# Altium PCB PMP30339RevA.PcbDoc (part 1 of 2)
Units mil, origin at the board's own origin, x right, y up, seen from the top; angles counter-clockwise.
Board outline 3000 x 2600 mil, 4 copper layers (Top Layer, Signal Layer 1, Signal Layer 2, Bottom Layer), stack 61.2 mil thick; 113 components, 43 nets, 222 pads, 187 vias.
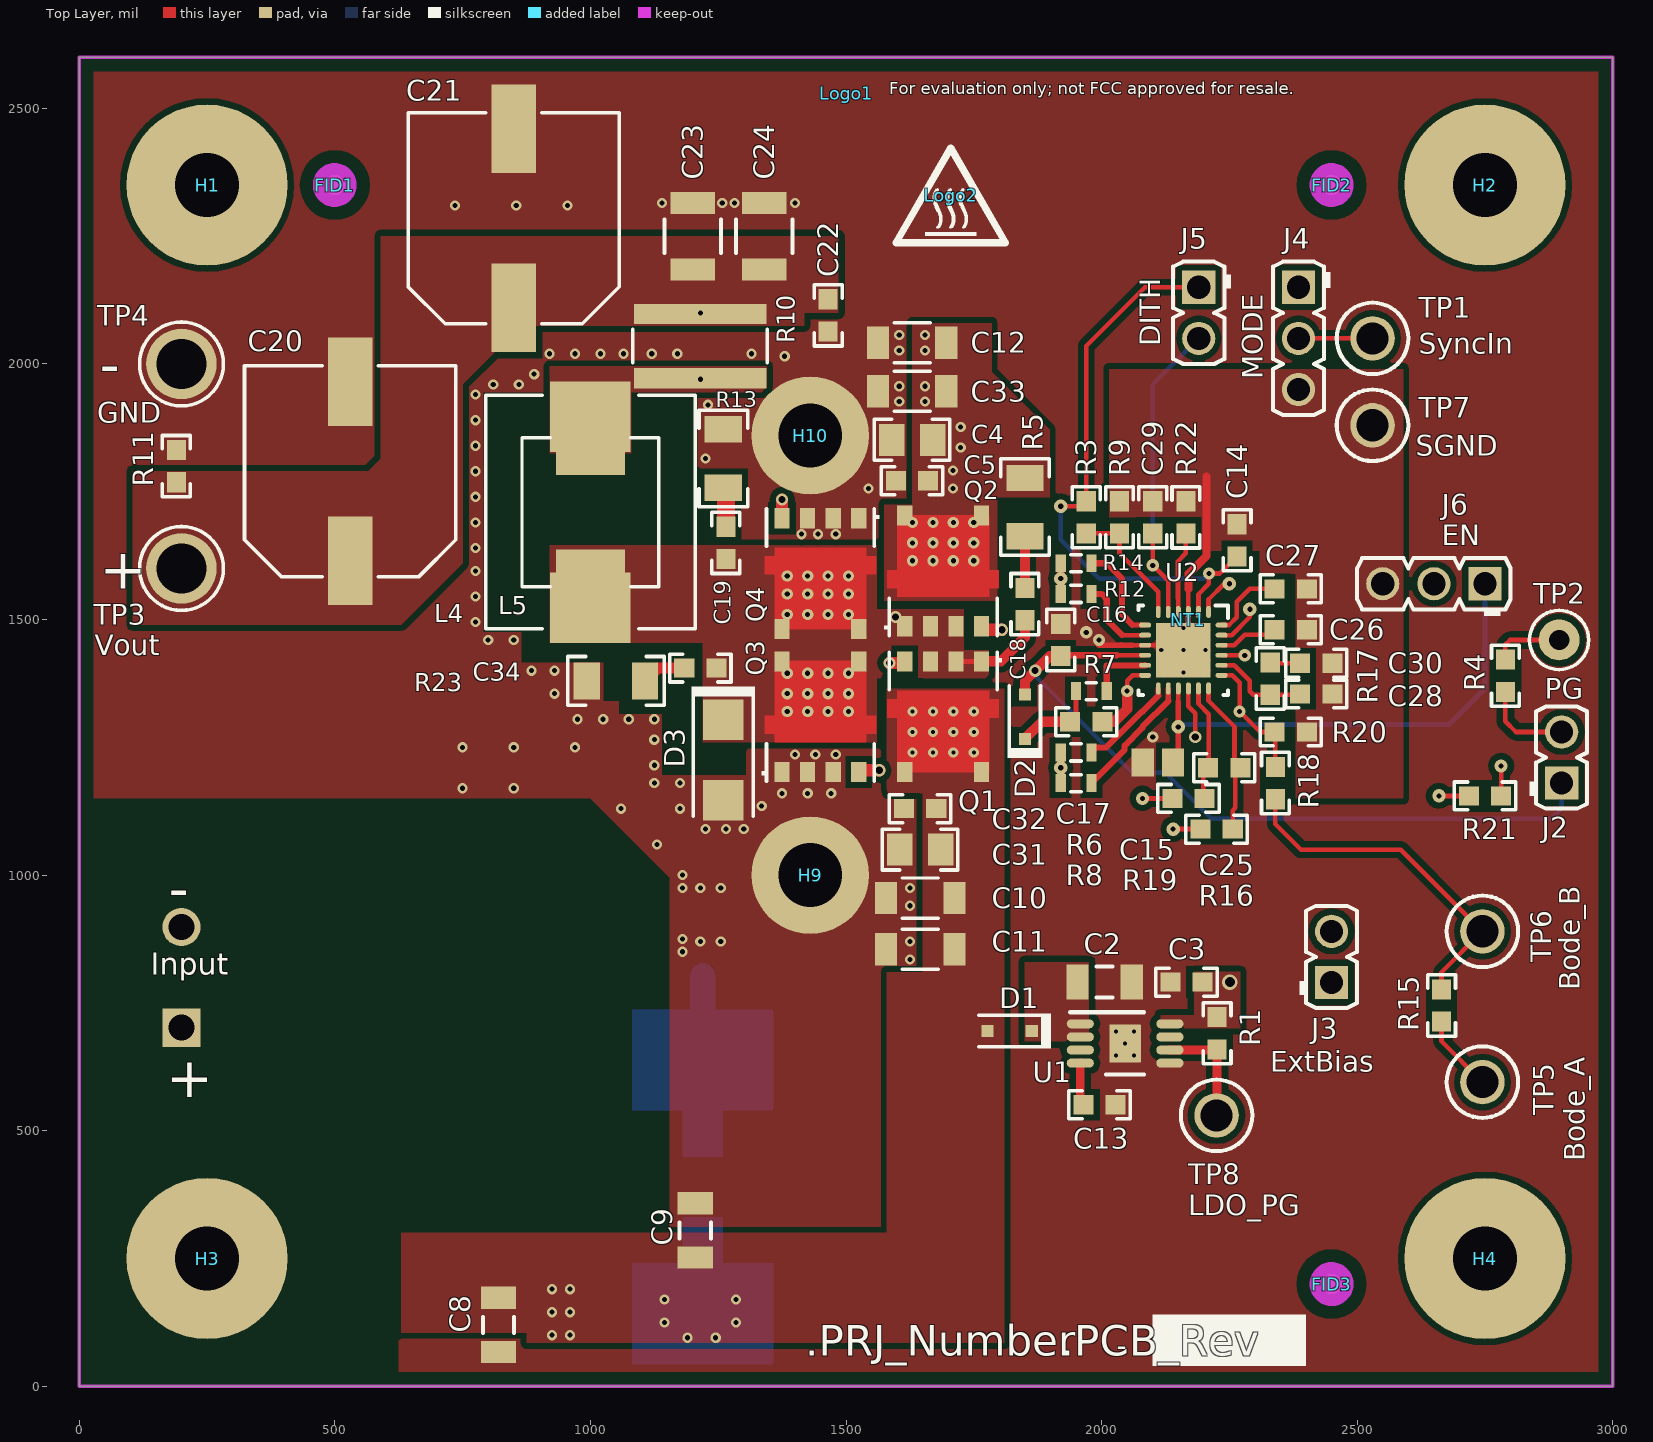
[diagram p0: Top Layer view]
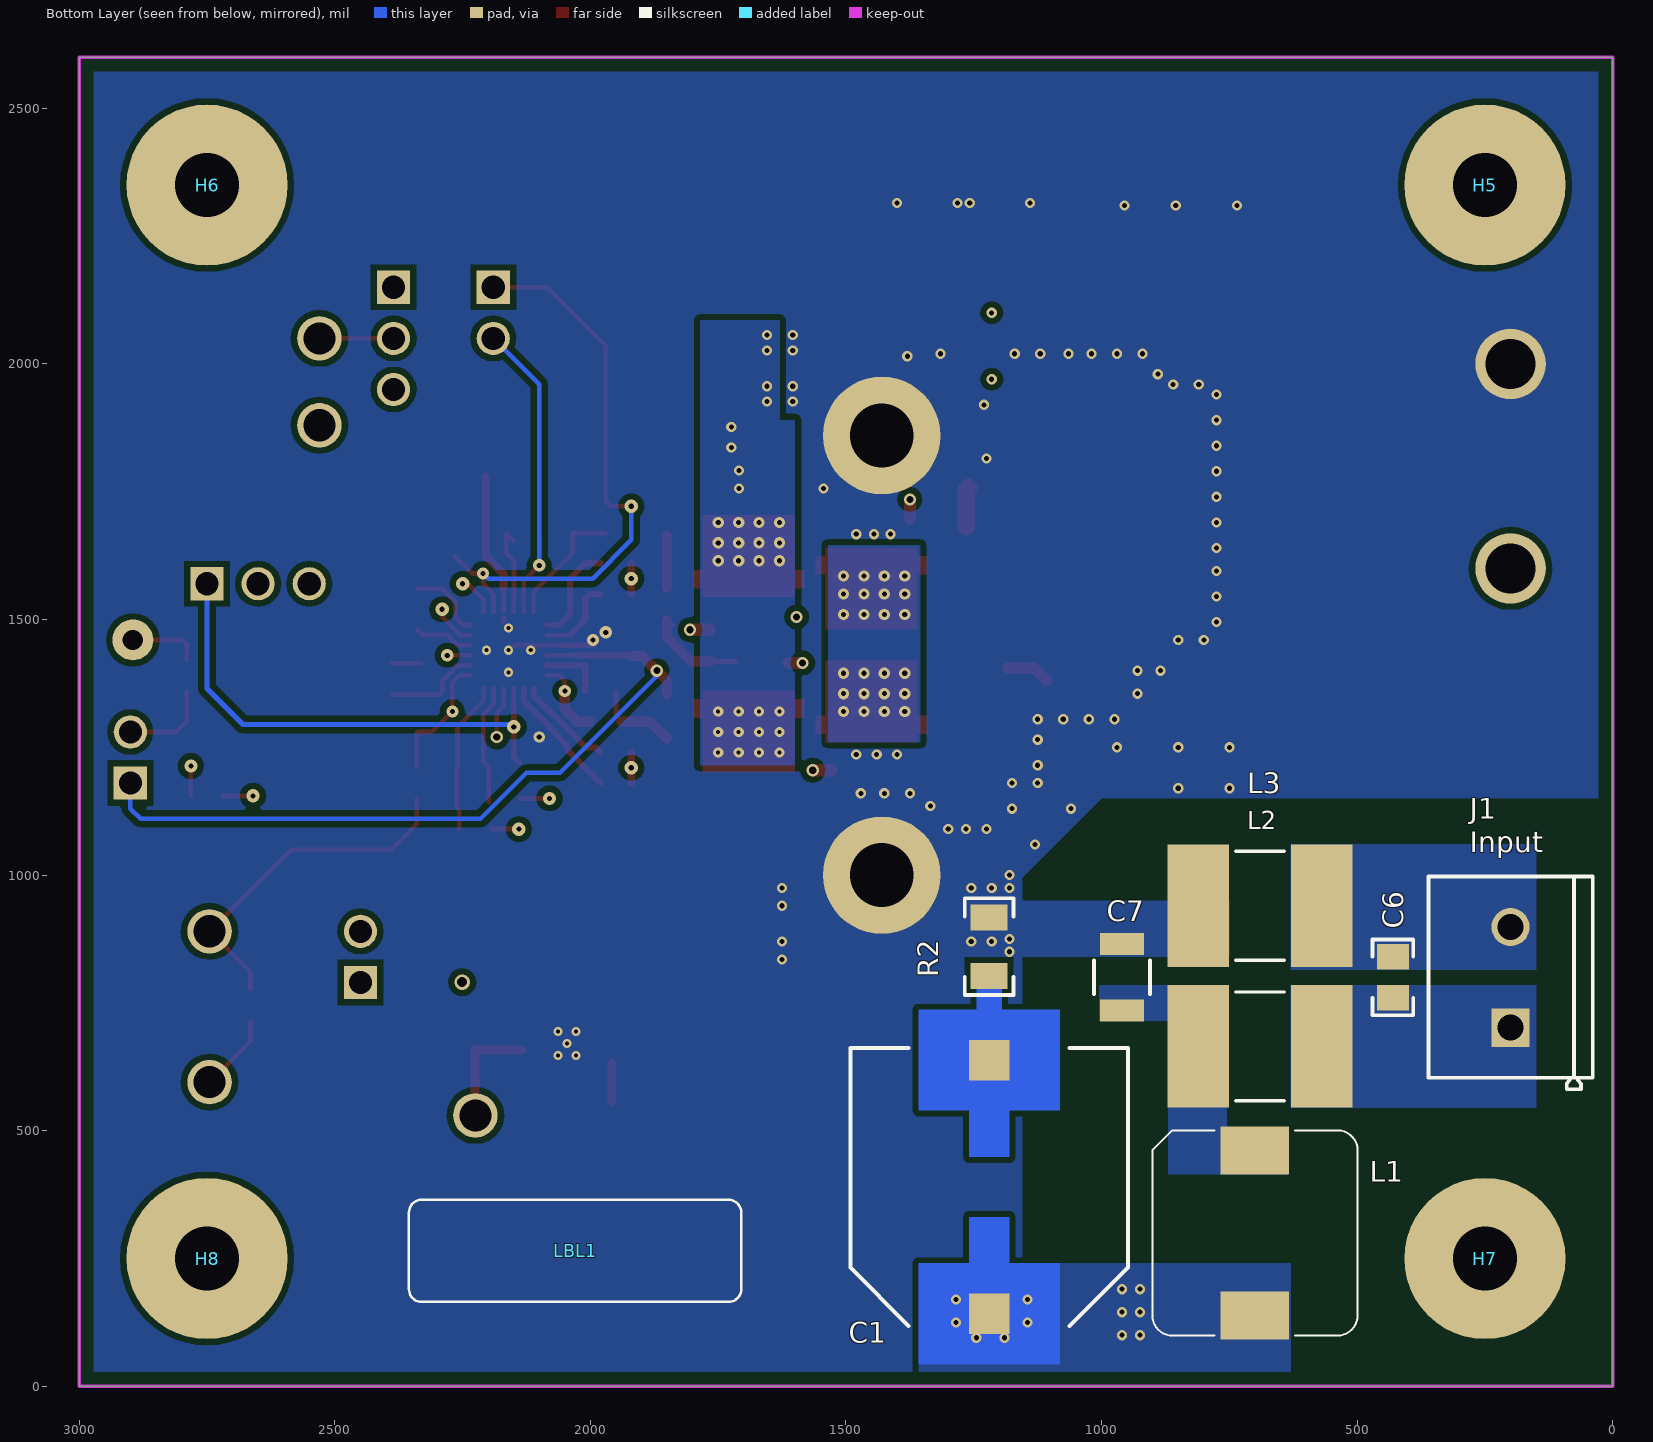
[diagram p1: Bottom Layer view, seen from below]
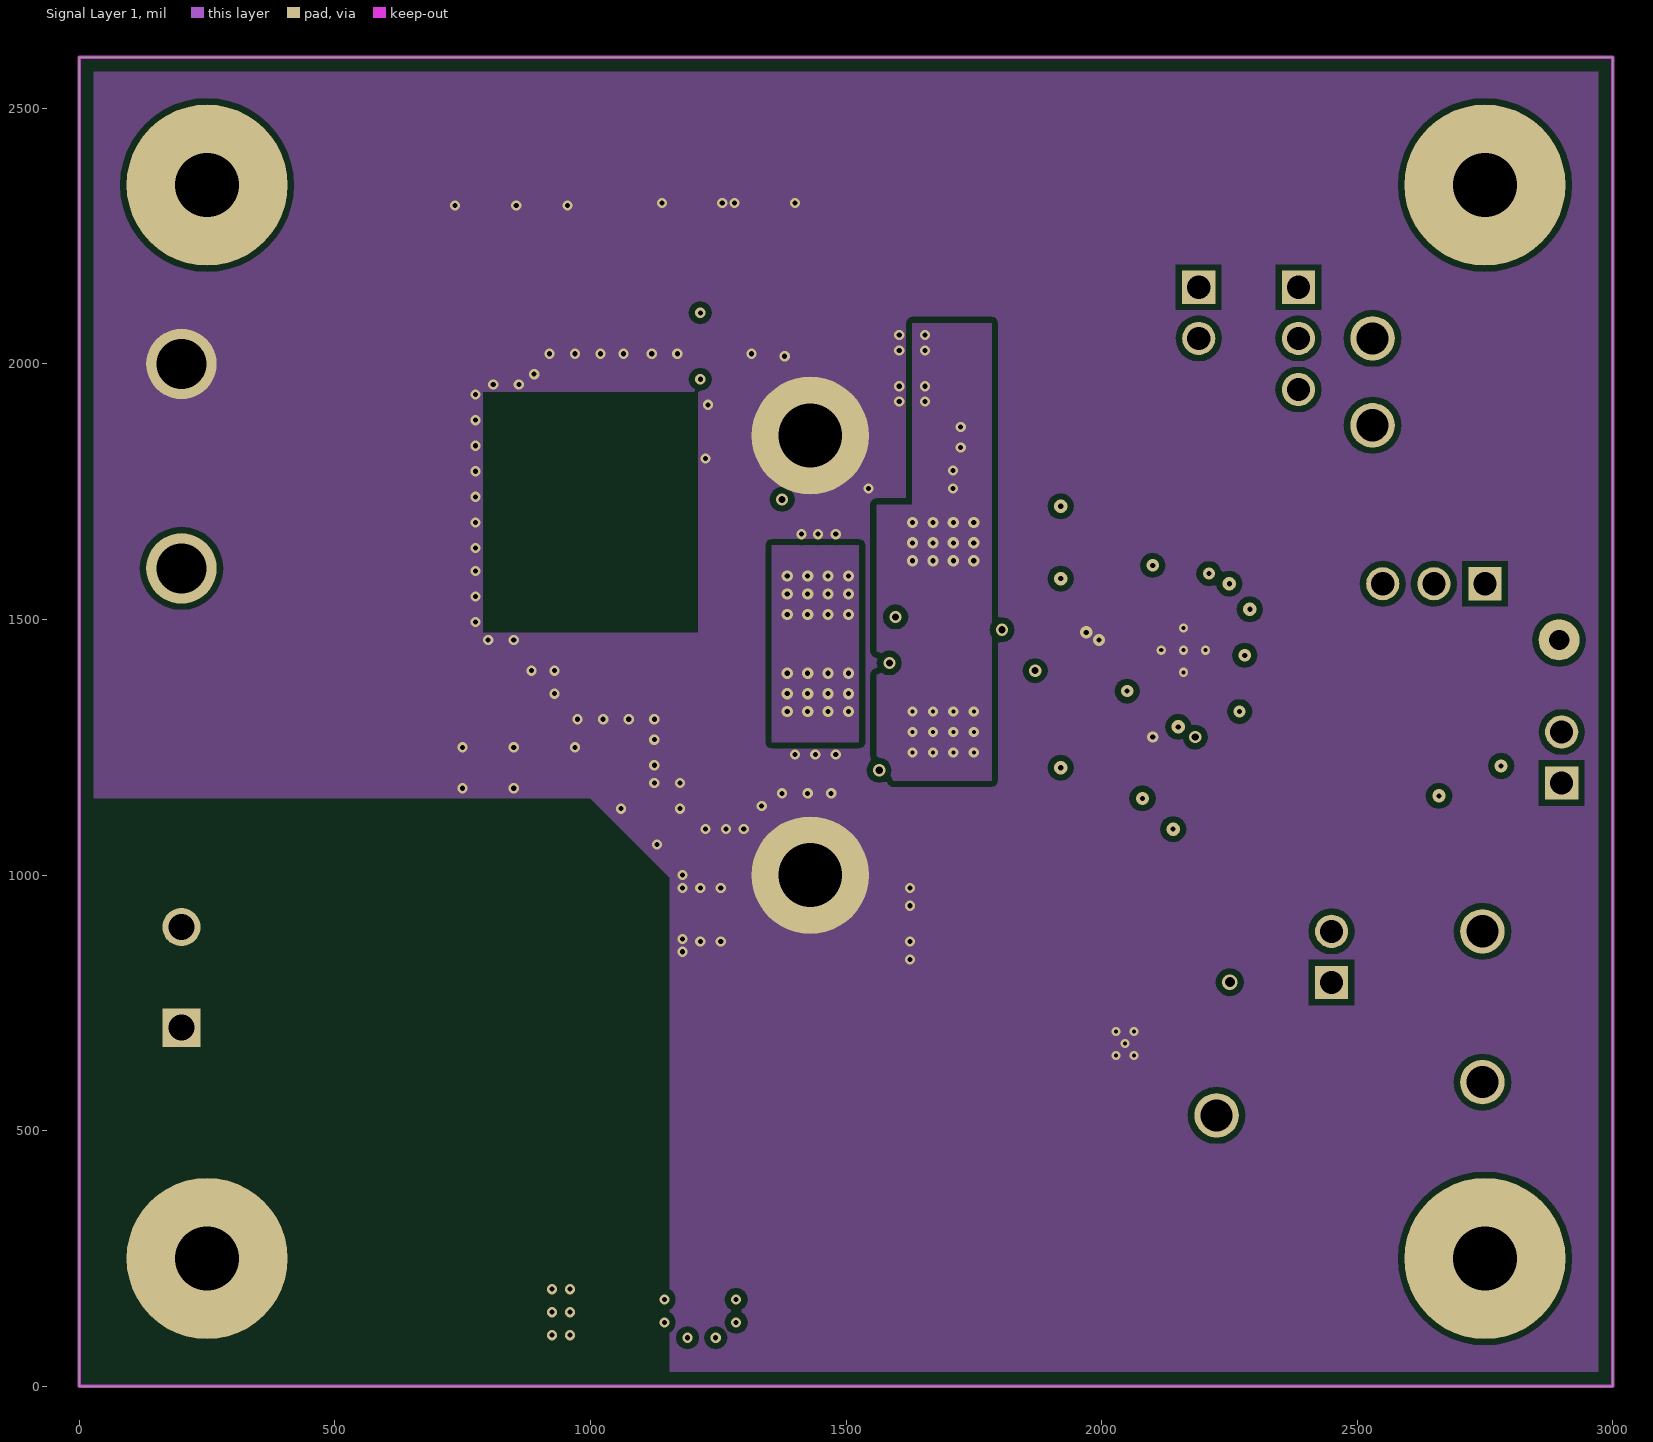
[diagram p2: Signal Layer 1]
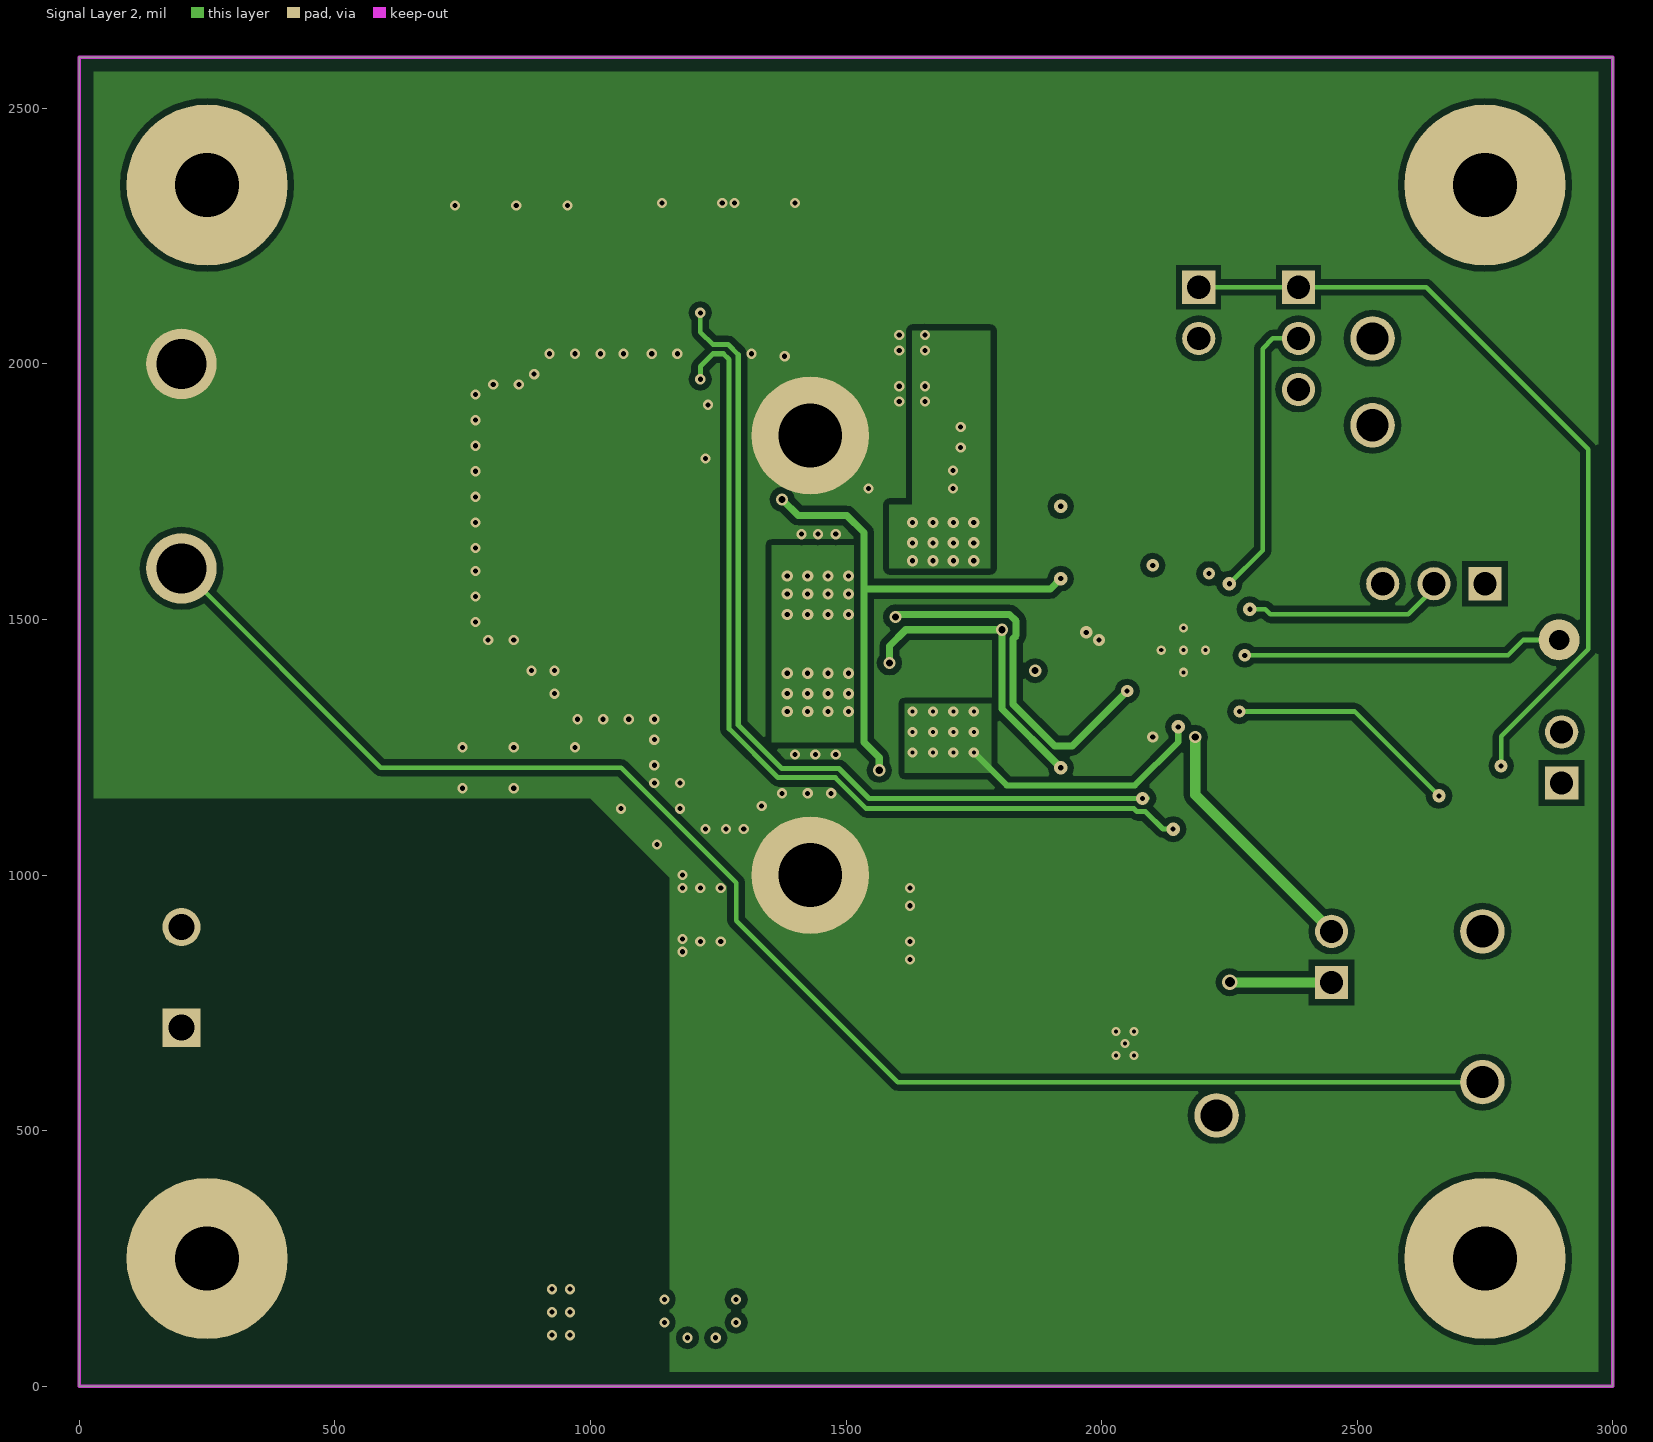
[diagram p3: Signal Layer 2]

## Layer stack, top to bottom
Top Solder: solder mask 0.4, Solder Resist, Dk 3.5
Top Layer: signal copper 2.8
Dielectric1: core 16, FR-4, Dk 4.8
Signal Layer 1: signal copper 2.8
Dielectric 3: prepreg 18, Dk 4.2
Signal Layer 2: signal copper 2.8
Dielectric 2: core 16, FR-4, Dk 4.2
Bottom Layer: signal copper 2.8
Bottom Solder: solder mask 0.4, Solder Resist, Dk 3.5

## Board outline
0,0 3000,0 3000,2600 0,2600

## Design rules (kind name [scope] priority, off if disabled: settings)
AcuteAngle [All] p1: minimum=4.50000000000000E+0001 checktracksonly=FALSE
AssemblyTestPointUsage [All] p1: valid=2
Clearance ClearanceNetTie [HasFootprint('RGE0024H') vs HasFootprint('Net-Tie_10mil')] p1: gap=0
Clearance Clearance_Keepouts [((IsTrack Or IsArc) And Not InPoly) And IsFree and IsKeepOut vs ((IsTrack Or IsArc) And Not InPoly) And IsFree and IsKeepOut] p2: gap=0
Clearance Clearance_BoardEdge_MountingHoles [OnCopper and InComponentClass('Mounting Holes') vs IsKeepOut] p3: gap=40
Clearance Clearance_BoardEdge_Poly [OnCopper and InPoly vs IsKeepOut] p4: gap=25
Clearance Clearance_BoardEdge [OnCopper and Not InComponentClass('Logo') and not InComponentClass('FiducialMark') and not InRegion(1000,500,4000,800) and Not IsKeepout vs IsKeepOut] p5: gap=40
Clearance Clearance_Poly [InPolygon] p6: gap=12
Clearance [All] p7: gap=7.87
ComponentClearance ComponentClearance_L2_L5 [HasFootprint('IHLP2525CZ') vs HasFootprint('IHLP-4040DZ')] p1: gap=0 collisioncheckmode=3 verticalgap=0 showdistances=FALSE
ComponentClearance ComponentClearanceNetTie [HasFootprint('RGE0024H') vs HasFootprint('Net-Tie_10mil')] p2: gap=0 collisioncheckmode=3 verticalgap=0 showdistances=FALSE
ComponentClearance ComponentClearance_MountingHoles_FiducialMarks [InComponentClass('Mounting Holes') vs InComponentClass('FiducialMark')] p3: gap=50 collisioncheckmode=3 verticalgap=10 showdistances=FALSE
ComponentClearance ComponentClearance_Shunt [InComponentClass('Header') vs InComponentClass('Shunt')] p4: gap=0 collisioncheckmode=3 verticalgap=0 showdistances=FALSE
ComponentClearance ComponentClearance_Logo [InComponentClass('Logo')] p5: gap=50 collisioncheckmode=3 verticalgap=10 showdistances=FALSE
ComponentClearance ComponentClearance_ScrewToNut [(HasFootprint('NY PMS 440 0025 PH')) vs (HasFootprint('Keystone_1902C'))] p6: gap=5 collisioncheckmode=3 verticalgap=10 showdistances=FALSE
ComponentClearance ComponentClearance_MountingHoles [InComponentClass('Mounting Holes')] p7: gap=100 collisioncheckmode=3 verticalgap=200 showdistances=FALSE
ComponentClearance ComponentClearance_SmallPassives [HasFootprint('0201*') or HasFootprint('0402*') or HasFootprint('0508') or HasFootprint('0603*') or HasFootprint('0612') or HasFootprint('0805*') or HasFootprint('0815*') or HasFootprint('0830*') or HasFootprint('1206*') or HasFootprint('1210*') or HasFootprint('1808*') or HasFootprint('1812*') or HasFootprint('1825*') or HasFootprint('2010*') or HasFootprint('2220*') or HasFootprint('2225*') or HasFootprint('2512*') or HasFootprint('2728*') or HasFootprint('3518*') vs HasFootprint('0201*') or HasFootprint('0402*') or HasFootprint('0508') or HasFootprint('0603*') or HasFootprint('0612') or HasFootprint('0805*') or HasFootprint('0815*') or HasFootprint('0830*') or HasFootprint('1206*') or HasFootprint('1210*') or HasFootprint('1808*') or HasFootprint('1812*') or HasFootprint('1825*') or HasFootprint('2010*') or HasFootprint('2220*') or HasFootprint('2225*') or HasFootprint('2512*') or HasFootprint('2728*') or HasFootprint('3518*')] p8: gap=20 collisioncheckmode=3 verticalgap=10 showdistances=FALSE
ComponentClearance ComponentClearance_THtoSMT [IsThruComponent vs IsSMTComponent] p9: gap=25 collisioncheckmode=3 verticalgap=30 showdistances=FALSE
ComponentClearance ComponentClearance_THtoTH [IsThruComponent vs IsThruComponent] p10: gap=25 collisioncheckmode=3 verticalgap=30 showdistances=FALSE
ComponentClearance [All] p11: gap=20 collisioncheckmode=3 verticalgap=10 showdistances=FALSE
DiffPairsRouting [All] p1: maxlimit=100 minlimit=10 mostfreqgap=10 toplayer_minwidth=15 toplayer_maxwidth=15 toplayer_prefwidth=15 midlayer1_minwidth=15 midlayer1_maxwidth=15 midlayer1_prefwidth=15 midlayer2_minwidth=15 midlayer2_maxwidth=15 midlayer2_prefwidth=15 bottomlayer_minwidth=15 bottomlayer_maxwidth=15 bottomlayer_prefwidth=15 maxuncoupledlength=1000
FabricationTestPointUsage TestPointUsage [All] p1: valid=2 allowmultiple=FALSE
FabricationTestpoint Testpoint [All] p1: side=3 testpointundercomponent=TRUE minsize=40 maxsize=100 preferedsize=60 minholesize=0 maxholesize=40 preferedholesize=32 testpointgrid=1 allowsidetop=TRUE allowsidebottom=TRUE usegrid=TRUE gridtolerance=0.01
FanoutControl Fanout_LCC [IsLCC] p1: bgadir=Out bgaviamode=Centered fanoutstyle=Auto fanoutdirection=Alternating viagrid=1 // Fanout_LCC (Default Rule)
FanoutControl Fanout_BGA [IsBGA] p2: bgadir=Out bgaviamode=Centered fanoutstyle=Auto fanoutdirection=Alternating viagrid=1 // Fanout_BGA (Default Rule)
FanoutControl Fanout_Default [All] p4: bgadir=Out bgaviamode=Centered fanoutstyle=Auto fanoutdirection=Alternating viagrid=1 // Fanout_Default (Default Rule)
FanoutControl Fanout_Small [(CompPinCount < 5)] p5: bgadir=Out bgaviamode=Centered fanoutstyle=Auto fanoutdirection=OutThenIn viagrid=1 // Fanout_Small (Default Rule)
HoleSize [All] p1: absolutevalues=TRUE maxlimit=251 minlimit=8 maxpercent=80.000 minpercent=20.000
MinimumAnnularRing MinimumAnnularRing_ThermalPadVias [IsVia and InAnyComponent] p1: minimumring=5
MinimumAnnularRing [All] p2: minimumring=5
MinimumSolderMaskSliver MinimumSolderMaskSliver_Logo [InComponentClass('Logo') vs InComponentClass('Logo')] p1: minsoldermaskwidth=0.7
MinimumSolderMaskSliver [All] p2: minsoldermaskwidth=3.94
PlaneConnect [All] p1: planeconnectstyle=Direct reliefexpansion=10 reliefentries=4 reliefconductorwidth=10 reliefairgap=10
PolygonConnect [All] p1: connectstyle=Direct reliefconductorwidth=10 reliefentries=4 polygonreliefangle="90 Angle" airgapwidth=10
RoutingVias ThermalPadVias [IsVia and InAnyComponent] p1: holewidth=8 width=18 viastyle="Through Hole" minholewidth=8 minwidth=18 maxholewidth=20 maxwidth=30
RoutingVias [All] p2: holewidth=16 width=34 viastyle="Through Hole" minholewidth=8 minwidth=18 maxholewidth=40 maxwidth=65
SilkToBoardRegionClearance [Not ((IsComment or IsDesignator) And (Hide <> 'False')) and not InRegion(1000,500,4000,800)] p1:
SilkToSilkClearance SilkToSilkClearance_Pb-FreeLogo [(HasFootprint('Pb-Free_Overlay_Medium') OR HasFootprint('Pb-Free_Overlay_Small')) vs (HasFootprint('Pb-Free_Overlay_Medium') OR HasFootprint('Pb-Free_Overlay_Small'))] p1: silktosilkclearance=0
SilkToSilkClearance [All] p2: silktosilkclearance=4
SilkToSolderMaskClearance "Silk to Solder Mask Opening" [All] p1: minsilkscreentomaskgap=3 clearancetoexposedcopper=FALSE
SolderMaskExpansion [All] p1: expansion=1.97
Width [All] p1: maxlimit=250 minlimit=6 preferedwidth=10 checkconnectedcopper=TRUE
15 further rules are at their usual default settings.

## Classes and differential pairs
component class "Mounting Holes": H1 H2 H3 H4
component class PMP20387-HW: FID1 FID2 FID3 H1 H2 H3 H4 H5 H6 H7 H8 H9 H10 LBL1 Logo1 Logo2 ZZ1 ZZ2 ZZ3 ZZ4 ZZ5 ZZ6 ZZ7 ZZ8
component class FiducialMark: FID1 FID2 FID3
component class AssemblyNote: ZX1 ZX2 ZX3 ZZ1 ZZ2 ZZ3 ZZ4 ZZ5 ZZ6 ZZ7 ZZ8
component class Label: LBL1
component class Header: J2 J3 J4 J5 J6
component class PMP20387: C1 C2 C3 C4 C5 C6 C7 C8 C9 C10 C11 C12 C13 C14 C15 C16 C17 C18 C19 C20 C21 C22 C23 C24 C25 C26 C27 C28 C29 C30 C31 C32 C33 C34 D1 D2 D3 J1 J2 J3 J4 J5 J6 L1 L2 L3 L4 L5 NT1 Q1 Q2 Q3 Q4 R1 R2 R3 R4 R5 R6 R7 R8 R9 R10 R11 R12 R13 R14 R15 R16 R17 R18 R19 R20 R21 R22 R23 TP1 TP2 TP3 TP4 TP5 TP6 TP7 TP8 U1 U2 ZX1 ZX2 ZX3

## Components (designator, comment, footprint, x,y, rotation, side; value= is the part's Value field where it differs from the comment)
C1 "UCZ1J181MNQ1MS" UCZ_1250x1350 1220,390 r90 bottom
C2 "C3216X7R2A105M160AA" 1206L 2005.96,790.71 r0 top
C3 "GRM188Z71C225KE43" 0603 2165.96,790.71 r180 top
C4 "C0805C104K1RACTU" 0805_HV 1629.28,1851.42 r180 top
C5 "C1608X7R2A103M" 0603 1629.28,1771.42 r180 top
C6 "C0805C104K1RACTU" 0805_HV 430,800 r90 bottom
C7 "C3225X7R1H106M250AC" 1210_280 960,800 r90 bottom
C8 "C3216X7R2A105M160AA" 1206L 820,120 r270 top
C9 "C3216X7R2A105M160AA" 1206L 1205,305 r90 top
C10 "UMK316AB7475KL-T" 1206_190 1645,955 r180 top
C11 "UMK316AB7475KL-T" 1206_190 1645,855 r180 top
C12 "UMK316AB7475KL-T" 1206_190 1629.28,2041.42 r180 top
C13 "GRM188R71E102KA01D" 0603 1995.96,550.71 r0 top
C14 "C0603C104K5RACTU" 0603 2265,1655 r270 top
C15 "GRM21BR72A474KA73L" 0805L 2110,1220 r0 top
C16 "GRM188R61C475KAAJ" 0603 1920,1460 r270 top
C17 "CGA3E3X7R1H474K080AB" 0603 1970,1300 r0 top
C18 "DNP" 0603 1850,1530 r270 top
C19 "DNP" 0603 1265,1650 r90 top
C20 "16SVPE470M" CAPSMT_62_JC0 530,1790 r90 top
C21 "16SVPE470M" CAPSMT_62_JC0 850,2285 r90 top
C22 "C0603C104K5RACTU" 0603 1465,2095 r270 top
C23 "LMK325ABJ107MMHT" 1210_280 1200,2250 r90 top
C24 "LMK325ABJ107MMHT" 1210_280 1340,2250 r90 top
C25 "06035A330JAT2A" 0603 2240,1210 r0 top
C26 "GRM188R71E683KA01D" 0603 2370,1480 r0 top
C27 "C1608X7R2A103M" 0603 2370,1560 r0 top
C28 "C1608C0G1H220J" 0603 2420,1354.45 r0 top
C29 "C1608X7R2A103M" 0603 2100,1700 r90 top
C30 "C1608X7R2A103M" 0603 2420,1414.45 r0 top
C31 "C0805C104K1RACTU" 0805_HV 1645,1050 r180 top
C32 "C1608X7R2A103M" 0603 1645,1130 r180 top
C33 "UMK316AB7475KL-T" 1206_190 1629.28,1946.42 r180 top
C34 "DNP" 0603 1215,1405 r180 top
D1 "PMEG6010CEJ,115" SOD-323F 1820,695 r180 top
D2 "PMEG6010CEJ,115" SOD-323F 1850,1310 r90 top
D3 "SSA210" SMA 1260,1225 r270 top
FID1 "Fiducial" Fiducial10-20 500,2350 r0 top
FID2 "Fiducial" Fiducial10-20 2450,2350 r0 top
FID3 "Fiducial" Fiducial10-20 2450,200 r0 top
H1 "NY PMS 440 0025 PH" "NY PMS 440 0025 PH" 250,2350 r0 top locked
H2 "NY PMS 440 0025 PH" "NY PMS 440 0025 PH" 2750,2350 r0 top locked
H3 "NY PMS 440 0025 PH" "NY PMS 440 0025 PH" 250,250 r0 top locked
H4 "NY PMS 440 0025 PH" "NY PMS 440 0025 PH" 2750,250 r0 top locked
H5 "1902C" Keystone_1902C 250,2350 r180 bottom locked
H6 "1902C" Keystone_1902C 2750,2350 r180 bottom locked
H7 "1902C" Keystone_1902C 250,250 r180 bottom locked
H8 "1902C" Keystone_1902C 2750,250 r180 bottom locked
H9 "PMSSS 440 0025 PH" B_F_PMSSS4400025PH 1430,1000 r0 top
H10 "PMSSS 440 0025 PH" B_F_PMSSS4400025PH 1430,1860 r0 top
J1 "Input" Phoenix_1729018 200,800 r90 bottom
J2 "PG" WURTH_61300211121 2900,1230 r90 top
J3 "ExtBias" WURTH_61300211121 2450,840 r90 top
J4 "MODE" WURTH_61300311121 2385,2050 r270 top
J5 "DITH" WURTH_61300211121 2190,2100 r270 top
J6 "EN" WURTH_61300311121 2650,1570 r180 top
L1 "7447798180" WE-PDF_1064 700,300 r270 bottom
L2 "74279224101" WE-MPSB_2220_1800 690,665 r0 bottom
L3 "74279224101" WE-MPSB_2220_1800 690,940 r0 bottom
L4 "DNP" IHLP-4040DZ 1000,1710 r90 top
L5 "IHLP2525CZEBR47M01" IHLP2525CZ 1000,1710 r90 top
LBL1 "" Label_650x200 2030,265 r180 bottom
Logo1 "FCC disclaimer" FCC_disclaimer 1500,2530 r0 top
Logo2 "CAUTION HOT SURFACE" IEC_HotSurface_Small 1705,2330 r0 top
NT1 "Net-Tie" Net-Tie_10mil 2169.84,1500 r270 top net-tie
Q1 "NVMFS5C468NLT1G" TRANS_DFN5 1690,1310 r270 top
Q2 "NVMFS5C468NLT1G" TRANS_DFN5 1690,1595 r90 top
Q3 "NVMFS5C468NLT1G" TRANS_DFN5 1450,1310 r90 top
Q4 "NVMFS5C468NLT1G" TRANS_DFN5 1450,1590 r270 top
R1 "CRCW060310K0FKEA" 0603 2225.96,690.71 r90 top
R2 "ERJ-8RQFR33V" 1206 1220,860 r270 bottom
R3 "CRCW06030000Z0EA" 0603 1970,1700 r270 top
R4 "CRCW060310K0FKEA" 0603 2790,1390 r90 top
R5 "DNP" 1206 1850,1720 r90 top
R6 "CRCW06030000Z0EA" 0603S 1950,1240 r180 top
R7 "CRCW06030000Z0EA" 0603S 1980,1360 r180 top
R8 "CRCW06030000Z0EA" 0603S 1950,1180 r0 top
R9 "DNP" 0603 2035,1700 r90 top
R10 "KRL6432E-M-R004-F-T1" 2512_WIDE 1215,2035 r90 top
R11 "CRCW0603100KFKEA" 0603 190,1800 r270 top
R12 "CRCW06030000Z0EA" 0603S 1950,1550 r180 top
R13 "DNP" 1206 1260,1815 r270 top
R14 "CRCW06030000Z0EA" 0603S 1950,1610 r0 top
R15 "CRCW0603200RFKEA" 0603 2665,745 r270 top
R16 "CRCW060349R9FKEA" 0603 2225,1090 r180 top
R17 "CRCW060310K0FKEA" 0603 2330,1384.45 r270 top
R18 "CRCW060321K0FKEA" 0603 2340,1180 r270 top
R19 "CRCW06030000Z0EA" 0603 2170,1150 r180 top
R20 "CRCW060312K1FKEA" 0603 2370,1280 r180 top
R21 "DNP" 0603 2750,1155 r180 top
R22 "CRCW060349K9FKEA" 0603 2165,1699.84 r270 top
R23 "DNP" 1206 1050,1380 r0 top
TP1 "SyncIn" Keystone5012 2530,2050 r270 top
TP2 "PG" Keystone5002 2895,1460 r270 top
TP3 "Vout" Keystone1598-2 200,1600 r180 top
TP4 "GND" Keystone1598-2 200,2000 r180 top
TP5 "Bode_A" Keystone5012 2745,595 r0 top
TP6 "Bode_B" Keystone5012 2745,890 r0 top
TP7 "SGND" Keystone5011 2530,1880 r0 top
TP8 "LDO_PG" Keystone5012 2225,530 r0 top
U1 "TPS7A6650QDGNRQ1" DGN0008D_N 2045.96,670.71 r0 top
U2 "LM5141QRGEQ1" RGE0024H 2160,1440 r270 top
ZX1 "VIN = 8 - 27VDC" AssemblyNote 180,2870 r0 top
ZX2 "Fsw = 2.2MHz" AssemblyNote 180,2680 r0 top
ZX3 "VOUT = 3.3VDC" AssemblyNote 180,2780 r0 top
ZZ1 "This Assembly Note is for PCB labels only" AssemblyNoteLabel 185,3938 r0 top
ZZ2 "These assemblies are ESD sensitive, ESD precautions shall be observed." AssemblyNote 180,3829.11 r0 top
ZZ3 "These assemblies must be clean and free from flux and all contaminants. Use of no clean flux is not acceptable." AssemblyNote 180,3737.97 r0 top
ZZ4 "These assemblies must comply with workmanship standards IPC-A-610 Class 2, unless otherwise specified." AssemblyNote 180,3646.84 r0 top
ZZ5 "Install Shunt Jumper SH-J1 onto J5" AssemblyNote 180,3555.7 r0 top
ZZ6 "Install Shunt Jumper SH-J3 onto J4 pin 2-3." AssemblyNote 185,3465 r0 top
ZZ7 "Install Shunt Jumper SH-J4 onto J6 pins 1-2." AssemblyNote 180,3370 r0 top
ZZ8 "Install Shunt Jumper SH-J6 onto J3." AssemblyNote 180,3265 r0 top

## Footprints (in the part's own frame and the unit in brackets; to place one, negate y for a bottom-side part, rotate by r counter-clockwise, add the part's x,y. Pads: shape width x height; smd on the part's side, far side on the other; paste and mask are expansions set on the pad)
0603 [mm] "0603 from SM-752 data"
  rect 1x0.95 smd: 1(-0.8,0) 2(0.8,0)
  silkscreen extent -1.52,-0.69 1.52,0.69, body extent -0.87,-0.47 0.87,0.47, height 1
0603S [mil]
  rect 20x35 smd: 1(-30,0) 2(30,0)
  silkscreen extent -10,-17 10,17, body extent -34,-19 34,19, height 39
0805_HV [mil] "0805 with 30mil clearance between pads"
  rect 50x63 smd: 1(-40,0) 2(40,0)
  silkscreen extent -74,-40 74,40, body extent -43,-29 43,29, height 57
0805L [mm] "0805 from SM-752 data"
  rect 1.1x1.4 smd: 1(-0.75,0) 2(0.75,0)
  body extent -1.1,-0.72 1.1,0.72, height 1.45
1206 [mm] "1206 from SM-752 data"
  rect 1.3x1.85 smd: 1(-1.45,0) 2(1.45,0)
  silkscreen extent -2.4,-1.21 2.4,1.21, body extent -1.7,-0.9 1.7,0.9, height 1.35
1206_190 [mm] "1206_190"
  rect 1.1x1.6 smd: 1(-1.7,0) 2(1.7,0)
  silkscreen extent -0.9,-1 0.9,1, body extent -1.75,-0.95 1.75,0.95, height 1.9
1206L [mm] "1206 from SM-752 data"
  rect 1.1x1.75 smd: 1(-1.35,0) 2(1.35,0)
  silkscreen extent -0.4,-0.77 0.4,0.77, body extent -1.7,-0.9 1.7,0.9, height 1.35
1210_280 [mm] "SMD, 2-Leads, Body 3.6x2.8mm, Height 2.8mm"
  rect 1.1x2.2 smd: 1(-1.65,0) 2(1.65,0)
  silkscreen extent -0.84,-1.4 0.84,1.4, body extent -1.8,-1.4 1.8,1.4, height 2.8
2512_WIDE [mm] "Ohmite recommended land pattern"
  rect 1x6.6 smd: 1(-1.6,0) 2(1.6,0)
  silkscreen extent -0.82,-3.32 0.82,3.35, body extent -1.65,-3.25 1.65,3.25, height 0.7
AssemblyNote [mil] "Assembly Note"
AssemblyNoteLabel [mil] "Assembly Note for PCB Labels"
B_F_PMSSS4400025PH [mil] "MACHINE SCREW PAN PHILLIPS 4-40"
  round 230 hole 125: 1(0,0)
  body extent -109,-109 110,110, height 79
CAPSMT_62_JC0 [mm] "10 x 12.2mm:  Chemi-Con JC0"
  rect 4.4x2.2 smd: 1(-4.45,0) 2(4.45,0)
  silkscreen extent -5.25,-5.25 5.25,5.25, body extent -5.25,-5.25 5.25,5.25, height 12.7
DGN0008D_N [mm] "TSOP, 8-Leads, Body 3x3mm, Pitch 0.65mm, Thermal Pad 1.89x1.57mm, IPC Medium Density"
  rrect100% 1.35x0.45 smd: 1(-2.225,0.975) 2(-2.225,0.325) 3(-2.225,-0.325) 4(-2.225,-0.975) 5(2.225,-0.975) 6(2.225,-0.325) 7(2.225,0.325) 8(2.225,0.975)
  rrect6% 1.57x1.89 smd: 9(0,0)
  silkscreen extent -2.73,-1.55 0.95,1.55, body extent -2.46,-1.5 2.46,1.5, height 1.1
FCC_disclaimer [mil]
Fiducial10-20 [mm]
  round 1 smd mask+0.5: 1(0,0)
  Top Layer keep-out circle w1.178: c0,0 r0.5
IEC_HotSurface_Small [mil]
  silkscreen extent -107,-93 107,92
IHLP2525CZ [mm] "Vishay Dale"
  rect 1.83x3.43 smd: 1(-2.77,0) 2(2.77,0)
  silkscreen extent -3.7,-3.4 3.7,3.4, body extent -3.62,-3.36 3.62,3.36, height 3
IHLP-4040DZ [mm] "Vishay Dale recommended land pattern.  Document 34192 rev 04-Jul-08"
  rect 3.5x4 smd: 1(-4.75,0) 2(4.75,0)
  silkscreen extent -5.8,-5.2 5.8,5.2, body extent -5.75,-5.15 5.75,5.15, height 4
Keystone1598-2 [mm] "Triple Turret"
  round 3.5 hole 2.5: 1(0,0)
  silkscreen extent -2.08,-2.08 2.08,2.08, body extent -1.6,-1.6 1.59,1.6, height 7.72
Keystone5002 [mil] "For Keystone 500x miniature loop terminals"
  round 80 hole 40: 1(0,0)
  silkscreen extent -58,-58 58,58, body extent -49,-49 49,49, height 182
Keystone5011 [mil] "Keystone Multipurpose loops"
  round 87 hole 63: 1(0,0)
  silkscreen extent -70,-70 70,70, body extent -63,-63 63,62, height 319
Keystone5012 [mil] "Keystone Multipurpose loops"
  round 87 hole 63: 1(0,0)
  silkscreen extent -70,-70 70,70, body extent -63,-63 63,62, height 319
Keystone_1902C [mil] "Hex Standoff, 4-40 threaded, nylon"
  body extent -145,-126 146,126, height 501
Label_650x200 [mil] "Thermal Transfer Label"
  round 1 on Mech14: 0(0,0)
  silkscreen extent -325,-100 325,100, body extent -325,-100 325,100, height 1
Net-Tie_10mil [mil] "10mil net tie, no solder mask opening, no solder paste"
  rect 10x10 smd paste-5 mask-5: 1(-10,0) 2(10,0)
  Top Layer region: -6,5 6,5 6,-5 -6,-5
"NY PMS 440 0025 PH" [mm] "4-40 nylon screw and mounting hole"
  round 8 hole 3.2: 1(0,0)
  body extent -3.3,-3.3 3.3,3.3, height 2.69
Phoenix_1729018 [mm] "Phoenix Contact"
  rect 1.905x1.905 hole 1.3: 1(-2.5,0)
  round 1.9 hole 1.3: 2(2.5,0)
  silkscreen extent -5.56,-4.08 5.01,4.07, body extent -5.56,-4.07 5.01,4.08, height 10
RGE0024H [mm] "QFN, 24-Leads, Body 4x4mm, Pitch 0.5mm, Thermal Pad 2.7x2.7mm, TI Recommended"
  oval 0.6x0.24 smd: 1(-1.9,1.25) 2(-1.9,0.75) 3(-1.9,0.25) 4(-1.9,-0.25) 5(-1.9,-0.75) 6(-1.9,-1.25) 13(1.9,-1.25) 14(1.9,-0.75) 15(1.9,-0.25) 16(1.9,0.25) 17(1.9,0.75) 18(1.9,1.25)
  oval 0.24x0.6 smd: 7(-1.25,-1.9) 8(-0.75,-1.9) 9(-0.25,-1.9) 10(0.25,-1.9) 11(0.75,-1.9) 12(1.25,-1.9) 19(1.25,1.9) 20(0.75,1.9) 21(0.25,1.9) 22(-0.25,1.9) 23(-0.75,1.9) 24(-1.25,1.9)
  rect 2.7x2.7 smd paste-1.35: 25(0,0)
  silkscreen extent -2.22,-2.22 2.22,2.22, body extent -2.07,-2.07 2.07,2.07, height 1.01
SMA [mm] "Molded Diode, 2-Leads, Body 4.3x2.6mm, IPC Medium Density, based on OnSemi component dimensions and land pattern"
  rect 2x2 smd: 1(-2,0) 2(2,0)
  silkscreen extent -3.66,-1.57 2.79,1.57, body extent -2.6,-1.3 2.6,1.3, height 2.42
SOD-323F [mm] "NXP recommended land pattern"
  rect 0.6x0.6 smd paste-0.05: 1(-1.1,0) 2(1.1,0)
  silkscreen extent -2.06,-0.86 1.53,0.86, body extent -1.35,-0.67 1.35,0.68, height 0.79
TRANS_DFN5 [mm] "OnSemi recommended land pattern Case 488AA Issue G dated 23 APR 2012"
  rect 1x0.75 smd mask+0.051: 1(-2.748,1.905) 2(-2.748,0.635) 3(-2.748,-0.635) 4(-2.748,-1.905) 5(2.748,-1.905) 6(2.748,1.905)
  Top Layer region: -1.282,2.28 2.773,2.28 2.773,-2.28 -1.282,-2.28
  Top Layer region: -0.858,2.775 0.047,2.775 0.047,-2.775 -0.858,-2.775
  silkscreen extent -3.21,-2.68 -1.35,2.93, body extent -3.05,-2.57 3.1,2.58, height 1.13
UCZ_1250x1350 [mm] "SMD, 2-Leads, Dia 12.5mm"
  rect 2x2 smd: 1(-6.3,0) 2(6.3,0)
  Top Layer region: 8.8,-3.5 8.8,3.5 3.8,3.5 3.8,1 1.5,1 1.5,-1 3.8,-1 3.8,-3.5
  Top Layer region: -8.8,-3.5 -8.8,3.5 -3.8,3.5 -3.8,1 -1.5,1 -1.5,-1 -3.8,-1 -3.8,-3.5
  silkscreen extent -6.9,-6.9 6.9,6.9, body extent -6.9,-6.9 6.9,6.9, height 14.51
WE-MPSB_2220_1800 [mm] "WURTH"
  rect 3.06x6.1 smd: 1(-3.065,0) 2(3.065,0)
  silkscreen extent -1.2,-2.7 1.2,2.7, body extent -3.05,-2.66 3.05,2.66, height 2.05
WE-PDF_1064 [mm] "WERTH"
  rect 2.4x3.4 smd: 1(-4.1,0) 2(4.1,0)
  silkscreen extent -5.1,-5.1 5.1,5.1, body extent -5.1,-5.1 5.1,5.1, height 6.35
WURTH_61300211121 [mm] "Header, 2.54mm, 2x1, TH"
  rect 1.65x1.65 hole 1.15: 1(-1.27,0)
  round 1.65 hole 1.15: 2(1.27,0)
  silkscreen extent -2.54,-1.27 2.54,1.6, body extent -2.54,-1.27 2.54,1.27, height 8.54
WURTH_61300311121 [mm] "Header, 2.54mm, 3x1, TH"
  rect 1.65x1.65 hole 1.15: 1(-2.54,0)
  round 1.65 hole 1.15: 2(0,0) 3(2.54,0)
  silkscreen extent -3.81,-1.27 3.81,1.6, body extent -3.81,-1.27 3.81,1.27, height 8.54

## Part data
C1: "CAP, AL, 180 µF, 63 V, +/- 20%, 0.2 ohm, AEC-Q200 Grade 1, SMD"
C2 C8 C9: "CAP, CERM, 1 µF, 100 V, +/- 20%, X7R, 1206"
C3: "CAP, CERM, 2.2 µF, 16 V, +/- 10%, X7R, 0603"
C4 C6 C31: "CAP, CERM, 0.1 µF, 100 V, +/- 10%, X7R, 0805"
C5 C27 C29 C30 C32: "CAP, CERM, 0.01 µF, 100 V, +/- 20%, X7R, 0603"
C7: "CAP, CERM, 10 µF, 50 V, +/- 20%, X7R, 1210"
C10 C11 C12 C33: "CAP, CERM, 4.7 µF, 50 V, +/- 10%, X7R, 1206_190"
C13: "CAP, CERM, 1000 pF, 25 V, +/- 10%, X7R, 0603"
C14 C22: "CAP, CERM, 0.1 µF, 50 V, +/- 10%, X7R, 0603"
C15: "CAP, CERM, 0.47 µF, 100 V, +/- 10%, X7R, 0805"
C16: "CAP, CERM, 4.7 µF, 16 V, +/- 10%, X5R, 0603"
C17: "CAP, CERM, 0.47 µF, 50 V, +/- 10%, X7R, AEC-Q200 Grade 1, 0603"
C18 C19 C34: library part GRM1885C2A102JA01D, "CAP, CERM, 1000 pF, 100 V, +/- 5%, C0G/NP0, 0603"
C20 C21: "CAP, Aluminum Polymer, 470 µF, 16 V, +/- 20%, 0.01 ohm, JC0 SMD"
C23 C24: "CAP, CERM, 100 µF, 10 V, +/- 20%, X5R, AEC-Q200 Grade 3, 1210"
C25: "CAP, CERM, 33 pF, 50 V, +/- 5%, C0G/NP0, 0603"
C26: "CAP, CERM, 0.068 µF, 25 V, +/- 10%, X7R, 0603"
C28: "CAP, CERM, 22 pF, 50 V, +/- 5%, C0G/NP0, 0603"
D1 D2: "Diode, Schottky, 60 V, 1 A, SOD-323F"
D3: "Diode, Schottky, 100 V, 2 A, AEC-Q101, SMA"
FID1 FID2 FID3: "Fiducial mark.  There is nothing to buy or mount."
H1 H2 H3 H4: "Machine Screw, Round, #4-40 x 1/4, Nylon, Philips panhead"
H5 H6 H7 H8: "Standoff, Hex, 0.5\"L #4-40 Nylon"
H9 H10: "MACHINE SCREW PAN PHILLIPS 4-40"
J1: library part 1729018, "TERM BLOCK 2POS 5mm, TH"
J2 J3 J5: library part 61300211121, "Header, 2.54 mm, 2x1, Gold, TH"
J4 J6: library part 61300311121, "Header, 2.54 mm, 3x1, Gold, TH"
L1: "Inductor, Shielded, Metal Composite, 1.8 µH, 12.8 A, 0.0038 ohm, SMD"
L2 L3: "Ferrite Bead, 100 ohm @ 100 MHz, 7 A, 2220 (H=1.8mm)"
L4: library part IHLP4040DZER2R0M11, "Inductor, Shielded Drum Core, Powdered Iron, 2 µH, 14 A, 0.0058 ohm, SMD"
L5: "Inductor, Shielded, Ferrite, 470 nH, 17.5 A, 0.0042 ohm, SMD"
LBL1: library part THT-14-423-10, "Thermal Transfer Printable Labels, 0.650\" W x 0.200\" H - 10,000 per roll"
Logo1: library part FCC_disclaimer, "FCC_disclaimer"
Logo2: library part IEC_HotSurface, "IEC 61010-1 Hot Surface Warning"
NT1: "Single point connection between nets."
Q1 Q2 Q3 Q4: library part NVMFS5C468NL, "MOSFET, N-CH, 40 V, 37 A, AEC-Q101, DFN5 5x6mm"
R1 R4 R17: "RES, 10.0 k, 1%, 0.1 W, 0603"
R2: "RES, 0.33, 1%, 0.25 W, 1206"
R3 R6 R7 R8 R12 R14 R19: "RES, 0, 5%, 0.1 W, 0603"
R5 R13 R23: library part CRM1206-JW-1R0ELF, "RES, 1.0, 5%, 0.5 W, 1206"
R9 R21: library part CRCW06030000Z0EA, "RES, 0, 5%, 0.1 W, 0603"
R10: library part KRL6432E-M-R007-F-T1, "RES, 0.004, 1%, 3 W, 2512 WIDE"
R11: "RES, 100 k, 1%, 0.1 W, 0603"
R15: "RES, 200, 1%, 0.1 W, 0603"
R16: "RES, 49.9, 1%, 0.1 W, 0603"
R18: "RES, 21.0 k, 1%, 0.1 W, 0603"
R20: "RES, 12.1 k, 1%, 0.1 W, 0603"
R22: "RES, 49.9 k, 1%, 0.1 W, 0603"
TP1 TP5 TP6 TP8: library part 5012, "Test Point, Multipurpose, White, TH"
TP2: library part 5002, "Test Point, Miniature, White, TH"
TP3 TP4: library part 1598-2, "Terminal, Turret, TH, Triple"
TP7: library part 5011, "Test Point, Multipurpose, Black, TH"
U1: "High-Voltage Ultralow-Iq Low-Dropout Regulator, DGN0008D"
U2: "IC, PWM, Buck Controller, w/ Dither"
ZX1 ZX2 ZX3: library part AssemblyNote, "This Assembly Note will show in the PcbDoc and associated outputs"
ZZ1: library part AssemblyNoteLabel
ZZ2 ZZ3 ZZ4 ZZ5 ZZ6 ZZ7 ZZ8: library part AssemblyNote

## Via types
v1: diameter 20, hole 10, Top Layer to Bottom Layer, tented both sides, 54 vias
v2: diameter 20, hole 10, Top Layer to Bottom Layer, 49 vias
v3: diameter 22, hole 10, Top Layer to Bottom Layer, 36 vias
v4: diameter 20, hole 8, Top Layer to Bottom Layer, 12 vias
v5: diameter 18, hole 8, Top Layer to Bottom Layer, 10 vias
v6: diameter 24, hole 10, Top Layer to Bottom Layer, tented both sides, 7 vias
v7: diameter 26, hole 10, Top Layer to Bottom Layer, tented both sides, 6 vias
v8: diameter 24, hole 14, Top Layer to Bottom Layer, 5 vias
v9: diameter 26, hole 10, Top Layer to Bottom Layer, 4 vias
v10: diameter 24, hole 14, Top Layer to Bottom Layer, tented both sides, 2 vias
v11: diameter 30, hole 20, Top Layer to Bottom Layer, 1 vias
v12: diameter 22, hole 10, Top Layer to Bottom Layer, tented both sides, 1 vias

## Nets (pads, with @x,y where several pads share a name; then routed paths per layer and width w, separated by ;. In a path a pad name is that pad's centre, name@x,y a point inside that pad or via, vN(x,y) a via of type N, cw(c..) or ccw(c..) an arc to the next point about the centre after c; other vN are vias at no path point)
+IN: C6.1 J1.1 L2.1
BODE: R15.1 R18.2 TP6.1 | length 687.1
  Top Layer w9: R18.2@2340,1148.5 2340,1100 2390,1050 2585,1050 TP6.1@2745,890 2665,810 R15.1@2665,776.5
COMP: C28.1 R17.2 U2.20 | length 187.7
  Top Layer w9: U2.20@2234.8,1410.47 2259.53,1410.47 2290,1380 2290,1360 2297.05,1352.95 R17.2@2330,1352.95 C28.1@2387.01,1352.95
CS: C25.2 R16.1 U2.18 | length 298.9
  Top Layer w9: U2.18@2209.21,1365.2 2209.21,1340.79 2260,1290 2260,1211.5 2261.5,1210 2261.5,1131.5 2256.5,1126.5 R16.1@2256.5,1090
DEMB: J4.2 TP1.1 U2.1 | length 788.2
  Top Layer w9: U2.1@2209.21,1514.8 2209.21,1539.21 2240,1570 v7(2250,1570) ; J4.2@2385,2050 TP1.1@2530,2050
  Signal Layer 2 w9: v7(2250,1570) 2315,1635 2315,2030 2335,2050 J4.2@2385,2050
DITH: C29.1 J5.2 U2.5 | length 647.6
  Top Layer w9: C29.1@2100,1668.5 v6(2100,1605.99) 2130.47,1575.51 U2.5@2130.47,1514.8
  Bottom Layer w9: v6(2100,1605.99) 2100,1960 J5.2@2190,2050
EN: J6.2 U2.23 | length 487.1
  Top Layer w9: U2.23@2234.8,1469.53 2254.93,1469.53 2272.28,1486.87 2272.28,1487.28 2290,1505 v7(2290,1520)
  Signal Layer 2 w9: v7(2290,1520) 2320,1520 2330,1510 2600,1510 2650,1560 J6.2@2650,1570 ; v7@2295,1515 v7@2300,1520
FB: R18.1 R20.2 R21.2 U2.19 | length 768.4
  Top Layer w9: U2.19@2234.8,1390.79 2255.35,1390.79 2270,1376.14 v6(2270,1320) 2310,1280 R20.2@2338.5,1280 2340,1278.5 R18.1@2340,1211.5
  Top Layer w10: v9(2660,1155) R21.2@2718.5,1155
  Signal Layer 2 w9: v6(2270,1320) 2495,1320 v9(2660,1155)
GND: C2.2 C3.2 C4.2 C5.2 C7.2 C8.2 C9.2 C10.2 C11.2 C12.2 C13.2 C15.1 C16.1 C20.2 C21.2 C22.2 C23.2 C24.2 C31.2 C32.2 C33.2 D3.2 H9.1 H10.1 L3.2 NT1.2 Q3.1 Q3.2 Q3.3 Q4.1 Q4.2 Q4.3 R2.1 R11.1 R13.1 R23.1 TP4.1 U1.5 U1.9 U2.9 U2.25 | length 155.4
  Top Layer w9: 2060,1450 U2.9@2085.2,1449.84 U2.25@2150.16,1449.84
  Top Layer w11: v6@1995,1450 2039.13,1450 ; 2038.97,1450.15 2039.13,1450 ; 2060,1450 2039.13,1450
  other v1: 1225,1090 1265,1090 1300,1090 1175,1130 1335,1135 1375,1160 1425,1160 1471,1160 1125,1180 1175,1180 1125,1215 1400,1236 1440,1236 1480,1236 1125,1265 975,1305 1025,1305 1075,1305 1125,1305 930,1355 885,1400 930,1400 800,1460 850,1460 775,1495 775,1545 775,1595 775,1640 1413,1667 1445,1667 1480,1667 775,1690 775,1740 775,1790 1225,1815 775,1840 775,1890 1230,1920 775,1940 810,1960 860,1960 890,1980 1380,2015 920,2020 970,2020 1020,2020 1065,2020 1120,2020 1170,2020 1315,2020 1140,2315 1258,2315 1282,2315 1400,2315
  other v2: 1625,835 1180,850 1215,870 1255,870 1625,870 1180,875 1625,940 1180,975 1215,975 1255,975 1625,975 1180,1000 1130,1060 1060,1130 750,1170 850,1170 750,1250 850,1250 970,1250 1544.28,1756.42 1604.28,1926.42 1604.28,1956.42 1604.28,2026.42 1604.28,2056.42 735,2310 855,2310 955,2310
  other v5: 2028.24,647.09 2063.67,647.09 2045.96,670.71 2028.24,694.33 2063.67,694.33 2160,1396.69 2116.69,1440 2160,1440 2203.31,1440 2160,1483.31
  other v6: 1995,1460 1970,1475
  other v12: 2100,1270
GND_IN: C6.2 J1.2 L3.1
HB: R7.1 U2.11 | length 125.5
  Top Layer w12: R7.1@2010,1360 2010,1410 2030,1410 2030.28,1410.28 2085.2,1410.28 U2.11@2085.2,1410.47
HG: Q1.4 Q2.4 R6.2 R8.1 | length 738.1
  Top Layer w14: Q1.4@1611.83,1415 Q1.4@1615,1418.17 ; R8.1@1920,1180 v9(1920,1210) R6.2@1920,1240
  Top Layer w24: v8(1585,1415) Q1.4@1611.83,1415 ; Q2.4@1766.83,1480 v8(1805,1480)
  Signal Layer 2 w14: v8(1585,1415) 1585,1447.99 1617.01,1480 v8(1805,1480) 1805,1325 ; 1822.5,1307.5 1805,1325 ; v9(1920,1210) 1805,1325
HO: R6.1 U2.13 | length 191.1
  Top Layer w10: 2110.79,1350.79 U2.13@2110.79,1365.2
  Top Layer w12: R6.1@1980,1240 1990,1250 2009.57,1250 2080,1320.43 2080.43,1320.43 2110.79,1350.79
HOL: R8.2 U2.14 | length 247.5
  Top Layer w10: 2130.47,1340.47 U2.14@2130.47,1365.2
  Top Layer w12: R8.2@1980,1180 1980,1180.06 2044.94,1245 2044.94,1253.31 2080,1288.36 2080,1290 2130.47,1340.47
LDO_IN: C2.1 D1.1 U1.1 U1.2
LDO_OUT: C3.1 J3.1 R1.2 U1.8 | length 198.3
  Signal Layer 2 w20: v11@2251.67,790 J3.1@2450,790
  other v11: 2250.96,790.71
LDO_PG: R1.1 TP8.1 U1.6 | length 219.4
  Top Layer w17: U1.6@2133.56,657.91 R1.1@2224.66,657.91
  Top Layer w18: TP8.1@2225.96,530.96 R1.1@2225.96,659.21
LG: Q3.4 Q4.4 R12.2 R14.1 | length 1191.3
  Top Layer w14: R12.2@1920,1550 v9(1920,1580) R14.1@1920,1610
  Top Layer w24: Q4.4@1375,1698.17 v8(1375,1735) ; Q3.4@1528.17,1205 v8(1565,1205)
  Signal Layer 2 w14: v8(1375,1735) 1406.61,1703.39 1501.61,1703.39 1535,1670 1535,1560 ; v8(1565,1205) 1565,1230 1535,1260 1535,1560 ; v9(1920,1580) 1900,1560 1535,1560
LO: R12.1 U2.8 | length 162
  Top Layer w9: 2040.47,1469.53 U2.8@2085.2,1469.53
  Top Layer w12: R12.1@1980,1550 2000,1550 2010,1540 2010,1500 2040.47,1469.53
LOL: R14.2 U2.7 | length 196.2
  Top Layer w9: 2060.79,1489.21 U2.7@2085.2,1489.21
  Top Layer w12: R14.2@1980,1610 2010,1610 2040,1580 2040,1510 2060.79,1489.21
NetC1_2: C1.2 R2.2 | length 164.9
  Bottom Layer w50: C1.2@1220,638.03 R2.2@1220,802.91
NetC7_1: C7.1 L1.1 L2.2
NetC13_1: C13.1 U1.4 | length 75.5
  Top Layer w17: C13.1@1958.36,556.81 U1.4@1958.36,632.32
NetC17_1: C17.1 D2.1 R7.2 | length 167.1
  Top Layer w9: C17.1@1938.5,1300 1950,1311.5 R7.2@1950,1360
  Top Layer w20: D2.1@1850,1266.69 1883.31,1300 C17.1@1938.5,1300
NetC18_1: C18.1 R5.1 | length 101.4
  Top Layer w20: C18.1@1850,1561.5 R5.1@1850,1662.91
NetC19_2: C19.2 R13.2 | length 78.5
  Top Layer w35: R13.2@1260,1757.91 1265,1752.91 C19.2@1265,1681.5
NetC30_1: C30.1 R17.1 | length 57
  Top Layer w9: R17.1@2331.5,1414.45 C30.1@2388.5,1414.45
NetC34_2: C34.2 R23.2 | length 86.8
  Top Layer w22: R23.2@1107.09,1380 1132.09,1405 C34.2@1183.5,1405
NetJ2_2: J2.2 R4.1 | length 176.4
  Top Layer w9: R4.1@2790,1358.5 2790,1300.63 2810.63,1280 J2.2@2900,1280
NetL4_2: L4.2 L5.2 R10.1 R16.2 | length 1822.2
  Top Layer w10: v7(2140,1090) R16.2@2193.5,1090
  Signal Layer 2 w10: v2(1215,1970) 1215,1995 1240,2020 1260,2020 1271.44,2008.56 1271.44,1286.29 1367.04,1190.68 1479.04,1190.68 1539.72,1130 2063.41,1130 2069.28,1124.13 2085.87,1124.13 2120,1090 v7(2140,1090)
